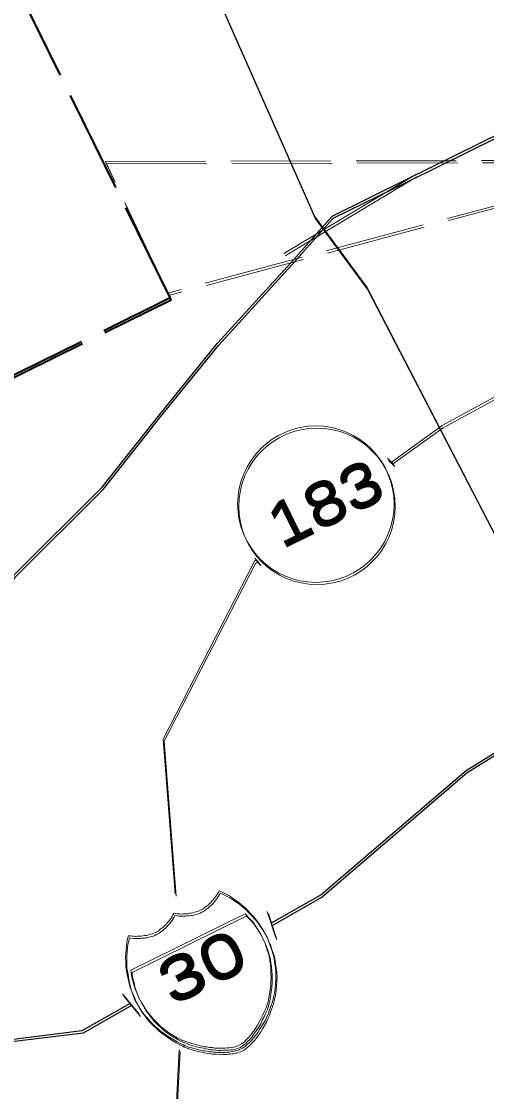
# Model space of a CAD drawing. Extents: x 2356606 to 2371222, y 6973096 to 6982644.
# Drawn here: x 2357229.6 to 2357285.3, y 6973619.6 to 6973747.7 of the extents above; entities that cross this region are included whole.
import ezdxf

# ---------------------------------------------------------------- set-up
doc = ezdxf.new("R2010")
doc.units = 0
doc.header["$LTSCALE"] = 2
doc.linetypes.add('LONG_DASHED', pattern=[7.5, 6, -1.5])
doc.layers.add('62', color=7, linetype='Continuous', lineweight=13)
doc.layers.add('63', color=7, linetype='Continuous', lineweight=13)

msp = doc.modelspace()

# ---------------------------------------------------------------- linework, layer by layer
at = {"layer": '62'}
for p, q in [((2357261.188, 6973719.601), (2357276.969, 6973729.069)), ((2357273.57, 6973695.123), (2357274.341, 6973694.374)), ((2357257.878, 6973682.937), (2357257.656, 6973682.778)), ((2357257.721, 6973683.161), (2357258.3, 6973682.493)), ((2357259.189, 6973640.875), (2357260.221, 6973637.722)), ((2357241.883, 6973631.004), (2357243.871, 6973628.549)), ((2357248.629, 6973624.349), (2357247.404, 6973600.032))]:
    msp.add_line(p, q, dxfattribs=at)
at = {"layer": '62', "linetype": 'LONG_DASHED', "lineweight": 40}
msp.add_lwpolyline([(2357063.437, 6973694.625), (2357091.678, 6973637.398), (2357247.577, 6973714.339), (2357219.335, 6973771.564), (2357063.154, 6973694.485)], dxfattribs=at)
at = {"layer": '62', "lineweight": 25}
for points in [[(2357246.593, 6973765.347), (2357264.847, 6973724.041), (2357271.1, 6973715.534)], [(2357222.847, 6973670.893), (2357228.918, 6973681.166), (2357239.427, 6973691.649), (2357246.285, 6973700.327), (2357253.234, 6973708.874), (2357262, 6973718.52), (2357266.949, 6973724.101), (2357275.91, 6973728.522), (2357290.215, 6973735.582), (2357301.579, 6973740.013), (2357308.151, 6973740.118), (2357312.029, 6973738.72)], [(2357271.1, 6973715.534), (2357293.579, 6973672.174), (2357318.873, 6973622.455), (2357356.041, 6973561.379), (2357384.703, 6973540.469)], [(2357321.156, 6973683.979), (2357307.783, 6973673.088), (2357282.978, 6973657.708), (2357265.622, 6973642.845), (2357259.668, 6973639.454)], [(2357242.801, 6973629.852), (2357237.017, 6973626.569), (2357228.509, 6973625.507), (2357217.835, 6973620.24), (2357195.98, 6973605.338)]]:
    msp.add_lwpolyline(points, dxfattribs=at)
at = {"layer": '62'}
for points in [[(2357340.392, 6973734.479), (2357322.629, 6973722.171), (2357280.124, 6973699.034), (2357274.052, 6973694.657)], [(2357257.656, 6973682.778), (2357246.728, 6973661.502), (2357248.172, 6973642.966)], [(2357248.886, 6973640.556), (2357249.107, 6973640.565), (2357249.308, 6973640.566), (2357249.5, 6973640.584), (2357249.721, 6973640.592), (2357249.923, 6973640.642), (2357250.094, 6973640.653), (2357250.294, 6973640.701), (2357250.466, 6973640.759), (2357250.667, 6973640.808), (2357250.849, 6973640.849), (2357251.031, 6973640.938), (2357251.212, 6973641.027), (2357251.373, 6973641.107), (2357251.533, 6973641.187), (2357251.695, 6973641.318), (2357251.838, 6973641.436), (2357251.988, 6973641.538), (2357252.151, 6973641.668), (2357252.283, 6973641.809), (2357252.425, 6973641.928), (2357252.566, 6973642.097), (2357252.717, 6973642.248), (2357252.839, 6973642.409), (2357252.962, 6973642.57), (2357253.081, 6973642.731), (2357253.194, 6973642.91), (2357253.336, 6973643.132), (2357253.438, 6973643.331), (2357253.798, 6973643.159), (2357254.192, 6973642.974), (2357254.571, 6973642.762), (2357254.944, 6973642.518), (2357255.323, 6973642.255), (2357255.737, 6973641.982), (2357256.116, 6973641.666), (2357256.497, 6973641.354), (2357256.869, 6973640.959), (2357257.227, 6973640.585), (2357257.587, 6973640.212), (2357257.919, 6973639.797), (2357258.227, 6973639.372), (2357258.517, 6973638.938), (2357258.775, 6973638.514), (2357259.034, 6973638.039), (2357259.254, 6973637.544), (2357259.473, 6973637.001), (2357259.661, 6973636.467), (2357259.829, 6973635.973), (2357259.969, 6973635.44), (2357260.045, 6973634.875), (2357260.123, 6973634.359), (2357260.212, 6973633.828), (2357260.23, 6973633.284), (2357260.205, 6973632.72), (2357260.18, 6973632.205), (2357260.132, 6973631.654), (2357260.045, 6973631.111), (2357259.933, 6973630.579), (2357259.799, 6973630.037), (2357259.615, 6973629.492), (2357259.463, 6973629.091), (2357259.319, 6973628.669), (2357259.145, 6973628.256), (2357258.962, 6973627.865), (2357258.728, 6973627.474), (2357258.495, 6973627.085), (2357258.271, 6973626.723), (2357258.048, 6973626.362), (2357257.805, 6973626.042), (2357257.562, 6973625.721), (2357257.309, 6973625.421), (2357257.027, 6973625.129), (2357256.793, 6973624.939), (2357256.531, 6973624.71), (2357256.289, 6973624.541), (2357256.056, 6973624.401)], [(2357256.056, 6973624.401), (2357255.886, 6973624.34), (2357255.745, 6973624.272), (2357255.553, 6973624.201), (2357255.391, 6973624.173), (2357255.23, 6973624.143), (2357255.03, 6973624.095), (2357254.818, 6973624.064), (2357254.605, 6973624.035), (2357254.384, 6973624.026), (2357254.175, 6973623.997), (2357253.92, 6973623.998), (2357253.719, 6973623.999), (2357253.48, 6973623.981), (2357253.247, 6973623.993), (2357253.004, 6973624.024), (2357252.756, 6973624.026), (2357252.512, 6973624.055), (2357252.251, 6973624.078), (2357251.98, 6973624.12), (2357251.759, 6973624.162), (2357251.518, 6973624.193), (2357251.253, 6973624.263), (2357250.984, 6973624.304), (2357250.773, 6973624.378), (2357250.523, 6973624.429), (2357250.291, 6973624.491), (2357250.031, 6973624.561), (2357249.819, 6973624.635), (2357249.578, 6973624.717), (2357249.367, 6973624.788), (2357249.166, 6973624.888), (2357248.946, 6973624.981), (2357248.513, 6973625.193), (2357248.092, 6973625.436), (2357247.67, 6973625.682), (2357247.287, 6973625.942), (2357246.876, 6973626.218), (2357246.487, 6973626.501), (2357246.114, 6973626.795), (2357245.745, 6973627.141), (2357245.416, 6973627.455), (2357245.053, 6973627.83), (2357244.746, 6973628.202), (2357244.435, 6973628.575), (2357244.134, 6973628.982), (2357243.875, 6973629.404), (2357243.596, 6973629.868), (2357243.356, 6973630.3), (2357243.158, 6973630.806), (2357242.978, 6973631.27), (2357242.791, 6973631.753), (2357242.66, 6973632.267), (2357242.535, 6973632.783), (2357242.436, 6973633.285), (2357242.359, 6973633.8), (2357242.27, 6973634.331), (2357242.253, 6973634.826), (2357242.235, 6973635.319), (2357242.247, 6973635.801), (2357242.291, 6973636.273), (2357242.345, 6973636.728), (2357242.388, 6973637.151), (2357242.479, 6973637.573), (2357242.563, 6973637.963), (2357242.804, 6973637.931), (2357243.045, 6973637.9), (2357243.277, 6973637.89), (2357243.457, 6973637.877), (2357243.678, 6973637.886), (2357243.881, 6973637.887), (2357244.094, 6973637.917), (2357244.312, 6973637.926), (2357244.494, 6973637.965), (2357244.686, 6973637.982), (2357244.886, 6973638.032), (2357245.058, 6973638.091), (2357245.26, 6973638.142), (2357245.442, 6973638.181), (2357245.603, 6973638.26), (2357245.806, 6973638.36), (2357245.948, 6973638.43), (2357246.125, 6973638.518), (2357246.27, 6973638.641), (2357246.43, 6973638.769), (2357246.582, 6973638.868), (2357246.723, 6973638.987), (2357246.875, 6973639.14), (2357247.037, 6973639.269), (2357247.139, 6973639.42), (2357247.291, 6973639.568), (2357247.431, 6973639.74), (2357247.573, 6973639.91), (2357247.677, 6973640.06), (2357247.805, 6973640.252), (2357247.907, 6973640.452), (2357248.031, 6973640.662), (2357248.252, 6973640.622), (2357248.453, 6973640.57), (2357248.684, 6973640.559), (2357248.886, 6973640.556)]]:
    msp.add_lwpolyline(points, dxfattribs=at)
at = {"layer": '62', "linetype": 'LONG_DASHED'}
for points in [[(2357239.812, 6973730.633), (2357306.835, 6973730.788), (2357247.289, 6973714.873)], [(2357239.812, 6973730.633), (2357306.835, 6973730.788), (2357247.289, 6973714.873), (2357239.812, 6973730.633)]]:
    msp.add_lwpolyline(points, close=True, dxfattribs=at)
at = {"layer": '62'}
msp.add_lwpolyline([(2357256.531, 6973640.568), (2357242.872, 6973633.826), (2357242.911, 6973633.593), (2357242.939, 6973633.283), (2357242.998, 6973632.96), (2357243.118, 6973632.568), (2357243.215, 6973632.114), (2357243.363, 6973631.61), (2357243.562, 6973631.104), (2357243.818, 6973630.53), (2357244.109, 6973629.995), (2357244.439, 6973629.431), (2357244.789, 6973628.925), (2357245.158, 6973628.431), (2357245.568, 6973627.957), (2357245.968, 6973627.552), (2357246.438, 6973627.106), (2357246.9, 6973626.73), (2357247.371, 6973626.386), (2357247.884, 6973626.062), (2357248.415, 6973625.749), (2357248.978, 6973625.472), (2357249.561, 6973625.258), (2357250.145, 6973625.046), (2357250.745, 6973624.891), (2357251.37, 6973624.746), (2357251.66, 6973624.665), (2357251.972, 6973624.643), (2357252.285, 6973624.569), (2357252.616, 6973624.558), (2357252.888, 6973624.518), (2357253.2, 6973624.495), (2357253.501, 6973624.494), (2357253.823, 6973624.503), (2357254.095, 6973624.511), (2357254.387, 6973624.53), (2357254.679, 6973624.549), (2357254.921, 6973624.568), (2357255.174, 6973624.617), (2357255.392, 6973624.676), (2357255.625, 6973624.765), (2357255.838, 6973624.844), (2357256.097, 6973625.024), (2357256.423, 6973625.232), (2357256.665, 6973625.505), (2357256.99, 6973625.813), (2357257.262, 6973626.125), (2357257.507, 6973626.497), (2357257.779, 6973626.857), (2357258.032, 6973627.258), (2357258.279, 6973627.68), (2357258.469, 6973628.099), (2357258.674, 6973628.501), (2357258.867, 6973628.924), (2357259.051, 6973629.316), (2357259.174, 6973629.676), (2357259.287, 6973630.058), (2357259.357, 6973630.371), (2357259.452, 6973630.943), (2357259.534, 6973631.486), (2357259.599, 6973632.02), (2357259.63, 6973632.562), (2357259.643, 6973633.045), (2357259.627, 6973633.538), (2357259.617, 6973634.011), (2357259.56, 6973634.483), (2357259.503, 6973634.957), (2357259.443, 6973635.381), (2357259.324, 6973635.824), (2357259.198, 6973636.238), (2357259.048, 6973636.641), (2357258.92, 6973637.055), (2357258.729, 6973637.437), (2357258.572, 6973637.809), (2357258.274, 6973638.365), (2357257.993, 6973638.828), (2357257.702, 6973639.265), (2357257.443, 6973639.636), (2357257.163, 6973639.951), (2357256.924, 6973640.183), (2357256.715, 6973640.407)], close=True, dxfattribs=at)
msp.add_circle((2357265.011, 6973689.618), 9.364, dxfattribs=at)
at = {"layer": '63'}
for p, q in [((2357261.058, 6973719.864), (2357276.839, 6973729.332)), ((2357273.44, 6973695.386), (2357274.211, 6973694.637)), ((2357257.748, 6973683.2), (2357257.526, 6973683.041)), ((2357257.591, 6973683.424), (2357258.17, 6973682.756)), ((2357259.059, 6973641.138), (2357260.091, 6973637.985)), ((2357241.753, 6973631.267), (2357243.741, 6973628.812)), ((2357248.499, 6973624.612), (2357247.274, 6973600.295))]:
    msp.add_line(p, q, dxfattribs=at)
at = {"layer": '63', "linetype": 'LONG_DASHED', "lineweight": 40}
msp.add_lwpolyline([(2357063.307, 6973694.888), (2357091.548, 6973637.661), (2357247.447, 6973714.602), (2357219.205, 6973771.827), (2357063.024, 6973694.748)], dxfattribs=at)
at = {"layer": '63', "lineweight": 25}
for points in [[(2357246.463, 6973765.61), (2357264.717, 6973724.304), (2357270.97, 6973715.797)], [(2357222.717, 6973671.156), (2357228.788, 6973681.429), (2357239.297, 6973691.912), (2357246.155, 6973700.59), (2357253.104, 6973709.137), (2357261.87, 6973718.783), (2357266.819, 6973724.364), (2357275.78, 6973728.785), (2357290.085, 6973735.845), (2357301.449, 6973740.276), (2357308.021, 6973740.381), (2357311.899, 6973738.983)], [(2357270.97, 6973715.797), (2357293.449, 6973672.437), (2357318.743, 6973622.718), (2357355.911, 6973561.642), (2357384.573, 6973540.732)], [(2357321.026, 6973684.242), (2357307.653, 6973673.351), (2357282.848, 6973657.971), (2357265.492, 6973643.108), (2357259.538, 6973639.717)], [(2357242.671, 6973630.115), (2357236.887, 6973626.832), (2357228.379, 6973625.77), (2357217.705, 6973620.503), (2357195.85, 6973605.601)]]:
    msp.add_lwpolyline(points, dxfattribs=at)
at = {"layer": '63'}
for points in [[(2357340.262, 6973734.742), (2357322.499, 6973722.434), (2357279.994, 6973699.297), (2357273.922, 6973694.92)], [(2357257.526, 6973683.041), (2357246.598, 6973661.765), (2357248.042, 6973643.229)], [(2357248.756, 6973640.819), (2357248.977, 6973640.828), (2357249.178, 6973640.829), (2357249.37, 6973640.847), (2357249.591, 6973640.855), (2357249.793, 6973640.905), (2357249.964, 6973640.916), (2357250.164, 6973640.964), (2357250.336, 6973641.022), (2357250.537, 6973641.071), (2357250.719, 6973641.112), (2357250.901, 6973641.201), (2357251.082, 6973641.29), (2357251.243, 6973641.37), (2357251.403, 6973641.45), (2357251.565, 6973641.581), (2357251.708, 6973641.699), (2357251.858, 6973641.801), (2357252.021, 6973641.931), (2357252.153, 6973642.072), (2357252.295, 6973642.191), (2357252.436, 6973642.36), (2357252.587, 6973642.511), (2357252.709, 6973642.672), (2357252.832, 6973642.833), (2357252.951, 6973642.994), (2357253.064, 6973643.173), (2357253.206, 6973643.395), (2357253.308, 6973643.594), (2357253.668, 6973643.422), (2357254.062, 6973643.237), (2357254.441, 6973643.025), (2357254.814, 6973642.781), (2357255.193, 6973642.518), (2357255.607, 6973642.245), (2357255.986, 6973641.929), (2357256.367, 6973641.617), (2357256.739, 6973641.222), (2357257.097, 6973640.848), (2357257.457, 6973640.475), (2357257.789, 6973640.06), (2357258.097, 6973639.635), (2357258.387, 6973639.201), (2357258.645, 6973638.777), (2357258.904, 6973638.302), (2357259.124, 6973637.807), (2357259.343, 6973637.264), (2357259.531, 6973636.73), (2357259.699, 6973636.236), (2357259.839, 6973635.703), (2357259.915, 6973635.138), (2357259.993, 6973634.622), (2357260.082, 6973634.091), (2357260.1, 6973633.547), (2357260.075, 6973632.983), (2357260.05, 6973632.468), (2357260.002, 6973631.917), (2357259.915, 6973631.374), (2357259.803, 6973630.842), (2357259.669, 6973630.3), (2357259.485, 6973629.755), (2357259.333, 6973629.354), (2357259.189, 6973628.932), (2357259.015, 6973628.519), (2357258.832, 6973628.128), (2357258.598, 6973627.737), (2357258.365, 6973627.348), (2357258.141, 6973626.986), (2357257.918, 6973626.625), (2357257.675, 6973626.305), (2357257.432, 6973625.984), (2357257.179, 6973625.684), (2357256.897, 6973625.392), (2357256.663, 6973625.202), (2357256.401, 6973624.973), (2357256.159, 6973624.804), (2357255.926, 6973624.664)], [(2357255.926, 6973624.664), (2357255.756, 6973624.603), (2357255.615, 6973624.535), (2357255.423, 6973624.464), (2357255.261, 6973624.436), (2357255.1, 6973624.406), (2357254.9, 6973624.358), (2357254.688, 6973624.327), (2357254.475, 6973624.298), (2357254.254, 6973624.289), (2357254.045, 6973624.26), (2357253.79, 6973624.261), (2357253.589, 6973624.262), (2357253.35, 6973624.244), (2357253.117, 6973624.256), (2357252.874, 6973624.287), (2357252.626, 6973624.289), (2357252.382, 6973624.318), (2357252.121, 6973624.341), (2357251.85, 6973624.383), (2357251.629, 6973624.425), (2357251.388, 6973624.456), (2357251.123, 6973624.526), (2357250.854, 6973624.567), (2357250.643, 6973624.641), (2357250.393, 6973624.692), (2357250.161, 6973624.754), (2357249.901, 6973624.824), (2357249.689, 6973624.898), (2357249.448, 6973624.98), (2357249.237, 6973625.051), (2357249.036, 6973625.151), (2357248.816, 6973625.244), (2357248.383, 6973625.456), (2357247.962, 6973625.699), (2357247.54, 6973625.945), (2357247.157, 6973626.205), (2357246.746, 6973626.481), (2357246.357, 6973626.764), (2357245.984, 6973627.058), (2357245.615, 6973627.404), (2357245.286, 6973627.718), (2357244.923, 6973628.093), (2357244.616, 6973628.465), (2357244.305, 6973628.838), (2357244.004, 6973629.245), (2357243.745, 6973629.667), (2357243.466, 6973630.131), (2357243.226, 6973630.563), (2357243.028, 6973631.069), (2357242.848, 6973631.533), (2357242.661, 6973632.016), (2357242.53, 6973632.53), (2357242.405, 6973633.046), (2357242.306, 6973633.548), (2357242.229, 6973634.063), (2357242.14, 6973634.594), (2357242.123, 6973635.089), (2357242.105, 6973635.582), (2357242.117, 6973636.064), (2357242.161, 6973636.536), (2357242.215, 6973636.991), (2357242.258, 6973637.414), (2357242.349, 6973637.836), (2357242.433, 6973638.226), (2357242.674, 6973638.194), (2357242.915, 6973638.163), (2357243.147, 6973638.153), (2357243.327, 6973638.14), (2357243.548, 6973638.149), (2357243.751, 6973638.15), (2357243.964, 6973638.18), (2357244.182, 6973638.189), (2357244.364, 6973638.228), (2357244.556, 6973638.245), (2357244.756, 6973638.295), (2357244.928, 6973638.354), (2357245.13, 6973638.405), (2357245.312, 6973638.444), (2357245.473, 6973638.523), (2357245.676, 6973638.623), (2357245.818, 6973638.693), (2357245.995, 6973638.781), (2357246.14, 6973638.904), (2357246.3, 6973639.032), (2357246.452, 6973639.131), (2357246.593, 6973639.25), (2357246.745, 6973639.403), (2357246.907, 6973639.532), (2357247.009, 6973639.683), (2357247.161, 6973639.831), (2357247.301, 6973640.003), (2357247.443, 6973640.173), (2357247.547, 6973640.323), (2357247.675, 6973640.515), (2357247.777, 6973640.715), (2357247.901, 6973640.925), (2357248.122, 6973640.885), (2357248.323, 6973640.833), (2357248.554, 6973640.822), (2357248.756, 6973640.819)]]:
    msp.add_lwpolyline(points, dxfattribs=at)
at = {"layer": '63', "linetype": 'LONG_DASHED'}
for points in [[(2357239.682, 6973730.896), (2357306.705, 6973731.051), (2357247.159, 6973715.136)], [(2357239.682, 6973730.896), (2357306.705, 6973731.051), (2357247.159, 6973715.136), (2357239.682, 6973730.896)]]:
    msp.add_lwpolyline(points, close=True, dxfattribs=at)
at = {"layer": '63'}
msp.add_lwpolyline([(2357256.401, 6973640.831), (2357242.742, 6973634.089), (2357242.781, 6973633.856), (2357242.809, 6973633.546), (2357242.868, 6973633.223), (2357242.988, 6973632.831), (2357243.085, 6973632.377), (2357243.233, 6973631.873), (2357243.432, 6973631.367), (2357243.688, 6973630.793), (2357243.979, 6973630.258), (2357244.309, 6973629.694), (2357244.659, 6973629.188), (2357245.028, 6973628.694), (2357245.438, 6973628.22), (2357245.838, 6973627.815), (2357246.308, 6973627.369), (2357246.77, 6973626.993), (2357247.241, 6973626.649), (2357247.754, 6973626.325), (2357248.285, 6973626.012), (2357248.848, 6973625.735), (2357249.431, 6973625.521), (2357250.015, 6973625.309), (2357250.615, 6973625.154), (2357251.24, 6973625.009), (2357251.53, 6973624.928), (2357251.842, 6973624.906), (2357252.155, 6973624.832), (2357252.486, 6973624.821), (2357252.758, 6973624.781), (2357253.07, 6973624.758), (2357253.371, 6973624.757), (2357253.693, 6973624.766), (2357253.965, 6973624.774), (2357254.257, 6973624.793), (2357254.549, 6973624.812), (2357254.791, 6973624.831), (2357255.044, 6973624.88), (2357255.262, 6973624.939), (2357255.495, 6973625.028), (2357255.708, 6973625.107), (2357255.967, 6973625.287), (2357256.293, 6973625.495), (2357256.535, 6973625.768), (2357256.86, 6973626.076), (2357257.132, 6973626.388), (2357257.377, 6973626.76), (2357257.649, 6973627.12), (2357257.902, 6973627.521), (2357258.149, 6973627.943), (2357258.339, 6973628.362), (2357258.544, 6973628.764), (2357258.737, 6973629.187), (2357258.921, 6973629.579), (2357259.044, 6973629.939), (2357259.157, 6973630.321), (2357259.227, 6973630.634), (2357259.322, 6973631.206), (2357259.404, 6973631.749), (2357259.469, 6973632.283), (2357259.5, 6973632.825), (2357259.513, 6973633.308), (2357259.497, 6973633.801), (2357259.487, 6973634.274), (2357259.43, 6973634.746), (2357259.373, 6973635.22), (2357259.313, 6973635.644), (2357259.194, 6973636.087), (2357259.068, 6973636.501), (2357258.918, 6973636.904), (2357258.79, 6973637.318), (2357258.599, 6973637.7), (2357258.442, 6973638.072), (2357258.144, 6973638.628), (2357257.863, 6973639.091), (2357257.572, 6973639.528), (2357257.313, 6973639.899), (2357257.033, 6973640.214), (2357256.794, 6973640.446), (2357256.585, 6973640.67)], close=True, dxfattribs=at)
msp.add_circle((2357264.881, 6973689.881), 9.364, dxfattribs=at)

# ---------------------------------------------------------------- texts
at = {"layer": '62'}
for s, width, p in [('183', 1.25, (2357260.817, 6973684.414)), ('30', 1.4, (2357247.702, 6973629.738))]:
    msp.add_text(s, height=5.099, rotation=26.268, dxfattribs=dict(at, width=width)).set_placement(p)
at = {"layer": '63'}
for s, width, p in [('183', 1.25, (2357260.687, 6973684.678)), ('30', 1.4, (2357247.572, 6973630.002))]:
    msp.add_text(s, height=5.099, rotation=26.268, dxfattribs=dict(at, width=width)).set_placement(p)

doc.saveas('drawing.dxf')
